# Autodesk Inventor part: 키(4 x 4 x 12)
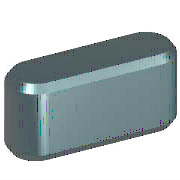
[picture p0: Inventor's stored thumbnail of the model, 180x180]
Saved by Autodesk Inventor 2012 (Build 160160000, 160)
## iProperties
IsCustomPart: 0
Created: 2009-02
Part Number: 키(4 x 4 x 12)
Material: 강, 연강
Description: 키 및 해당 키홈
Document SubType Name: Modeling
Standard: KS B 1311
Designer: KYOUNG IL JANG
Standards Organization: KS
Language: ko-KR
Size Designation: 4 x 4 x 12
Categories: <MemberInstance><Categories><Category DisplayName="샤프트 부품" InternalName="7f7aeb1f-a693-4053-b835-cee3144e0d98" Mnemonic="SHFT"><Category DisplayName="키" Interna
Density: 7.86 g/cm^3
Mass: 1.38739 g
Surface Area: 1.94869 cm^2
Volume: 0.176513 cm^3
Author: KYOUNG IL JANG
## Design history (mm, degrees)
workplane "Work Plane1"
workplane "Work Plane2"
sketch "스케치1"
  geometry: L1 (2, 2)-(10, 2); L2 (10, -2)-(2, -2); L3 (0, 9.4)-(0, -7.4) reference; L4 (-5, 0)-(30, 0) reference; L5 (12, 0)-(12, 7); A1 r 2 centre (2, 0) between (2, 2) and (2, -2); A2 r 2 centre (10, 0) between (10, -2) and (10, 2)
  constraints: 6 end point, 5 point on circle, 4 tangent, 3 point on line, 2 centre point, 1 horizontal, 1 parallel, 1 perpendicular
  dimensions: "d0" = 2 radius of A1 (= 0.5 x PB); "d13" = 2 radius of A2 (= 0.5 x PB); "d14" = 12 distance between parallel lines of L5 L3 (= NLG)
extrude "본체1" new body sketch "스케치1" taper "d3" = 0 deg; stored distance "d4" = 10
workplane "Work Plane3"
body "Solid1"
chamfer "모따기1" distance "d8" = 0.25 (= PHH); stored, may be unused: second distance "d9" = 0.25 (= PHH), angle "d15" = 45 deg
other parameters: "d1" = -2.5 (= -PNT), "d2" = 1.5 (= PH - PNT), "NLG" = 12 [user parameter; used in 3 equation terms], "PB" = 4 [user parameter; used in 2 equation terms], "PNT" = 2.5 [user parameter; used in 2 equation terms], "PH" = 4 [user parameter; used in 1 equation term], "PHH" = 0.25 [user parameter; used in 2 equation terms], "d10" = 0, "d16" = 0, "d17" = 0, "d18" = 0, "PLB2" = 12 (= NLG) [user parameter], "WDMAX" = 12 [user parameter], "PLB1" = 12 (= NLG) [user parameter], "RR" = 0.08 [user parameter], "PUEB" = 1.8 [user parameter]
